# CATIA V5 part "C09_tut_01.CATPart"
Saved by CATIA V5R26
Part number: Part1
Bounding box of the stored display mesh (mm): x -75 to 140, y -40 to 40, z 0 to 100
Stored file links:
  D:\_Deepak\CATIA\CATIA V5 2015 Parts Files\Tutorial Files\Tutorials\c09_catia_v5_6r2015_tut\C09_tut_01.CATPart
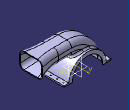
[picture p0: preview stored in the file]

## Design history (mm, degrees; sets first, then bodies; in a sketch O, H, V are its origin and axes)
Body1 (main body)
  Sketch1 on zx-plane, origin (0, 0, 0), H (-1, 0, 0), V (0, 0, 1)
    arc A1 centre (0, 0) radius 60 from (60, 0) to (-60, 0) ccw
    line L1 (-60, 0) -> (60, 0)
    point P1 (-60, 0)
    radius A1 = 60
    coincidence: P1 H
    horizontal: L1 H
  Pad1: profile Sketch1, direction (0, 1, 0), length 40, mirrored extent
  Sketch2 on zx-plane, origin (0, 0, 0), H (-1, 0, 0), V (0, 0, 1)
    point P1 (-82, 100)
    line L1 (-82, 100) -> (-40, 100)
    arc A1 centre (-40, 0) radius 100 from (-40, 100) to (60, 0) cw
    point P4 (60, 0)
    reference projected line E1 (-60, 0) -> (60, 0) from edge [face of Pad1 from Sketch1.L1 | end face of Pad1]
    reference projected point E2 (60, 0) from edge [face of Pad1 from Sketch1.A1 | face of Pad1 from Sketch1.L1]
    reference projected arc E3 centre (0, 0) radius 60 from (60, 0) to (-60, 0) ccw from edge [face of Pad1 from Sketch1.A1 | end face of Pad1]
    distance P1 E1 = 100
    distance P1 V = 82
    horizontal: L1 H
    tangency: A1 L1, A1 E3
    coincidence: P4 E2
  Plane1: type Normal, Curve Sketch2, RefPoint Sketch2.P1, Ratio 0
  Sketch3 on Plane1, origin (82, 0, 0), H (0, 1, 0), V (0, 0, 1)
    line L1 (-29, 100) -> (29, 100)
    line L2 (29, 100) -> (29, 58)
    line L3 (29, 58) -> (-29, 58)
    line L4 (-29, 58) -> (-29, 100)
    reference projected point E1 (0, 100) from Sketch2.P1
    distance L4 V = 29
    length L1 = 58
    length L2 = 42
    horizontal: L1 H, L3 H
    vertical: L2 V, L4 V
    coincidence: L1 E1
  Rib1: profile Sketch3, centre curve Sketch2
  Plane2: type Offset, RefPlane face of Rib1, Offset 58, reversed
  Sketch4 on Plane2, origin (140, 0, 0), H (0, -1, 0), V (0, 0, 1)
    line L1 (36.53, 100) -> (-36.47, 100)
    line L2 (-36.47, 100) -> (-36.47, 47)
    line L3 (-36.47, 47) -> (36.53, 47)
    line L4 (36.53, 47) -> (36.53, 100)
    reference projected line E1 (40, 0) -> (-40, 0) from edge [face of Rib1 | face of Pad1 from Sketch1.A1]
    distance L4 V = 36.53
    distance L1 E1 = 100
    length L2 = 53
    length L1 = 73
    horizontal: L1 H, L3 H
    vertical: L2 V, L4 V
  Loft1: solid, Sections ({boundary Boundary {extract ExtractElem face of Rib1}}; Sketch4), StartFace face of Rib1
  Fillet1: radius 15, on edge [face of Rib1 | face of Rib1] (x3); edge [face of Loft1 | face of Loft1]
  Shell1: ExtOffset 0, Face (face of Rib1; face of Loft1), IntOffset 2.5
  Fillet2: radius 5, on edge [face of Pad1 from Sketch1.A1 | face of Fillet1]
  Sketch5 on end face of Pad1, origin (0, 40, 0), H (-1, 0, 0), V (0, 0, 1)
    arc A1 centre (0, 0) radius 49 from (49, 0) to (-49, 0) ccw
    line L1 (-49, 0) -> (49, 0)
    point P1 (-49, 0)
    radius A1 = 49
    coincidence: P1 H
    horizontal: L1 H
  Pocket1: profile Sketch5, direction (0, -1, 0), through (limit type 6)
  Sketch6 on start face of Pad1, origin (0, -40, 0), H (1, 0, 0), V (0, 0, 1)
    circle A1 centre (0, 0) radius 15
    radius A1 = 15
  Pocket2: profile Sketch6, direction (0, 1, 0), through (limit type 6)
  Sketch7 on end face of Pad1, origin (0, 40, 0), H (-1, 0, 0), V (0, 0, 1)
    line L1 (60, 0) -> (75, 0)
    line L2 (75, 0) -> (75, 4)
    line L3 (75, 4) -> (59.8665, 4)
    point P4 (59.8665, 4)
    reference projected line E1 (-60, 0) -> (60, 0) from edge [face of Rib1 | end face of Pad1]
    reference intersected line E2 (60, 0) -> (-60, 0) from face of Rib1
    reference projected arc E3 centre (0, 0) radius 60 from (60, 0) to (-60, 0) ccw from edge [face of Pad1 from Sketch1.A1 | end face of Pad1]
    projected arc E4 centre (0, 0) radius 60 from (60, 0) to (-60, 0) ccw from edge [face of Pad1 from Sketch1.A1 | end face of Pad1]
    projected arc E5 centre (0, 0) radius 60 from (60, 0) to (59.8665, 4) ccw from edge [face of Pad1 from Sketch1.A1 | end face of Pad1]
    length L2 = 4
    distance L2 V = 75
    horizontal: L1 H, L3 H
    vertical: L2 V
    coincidence: L1 E1, L1 E2, P4 E3
  Pad2: profile Sketch7, direction (0, -1, 0), length 80
  Mirror1: of Pad2, about yz-plane
  Sketch8 on face of Mirror1, origin (0, 0, 4), H (1, 0, 0), V (0, 1, 0)
    point P1 (-67, 30)
    reference projected line E1 (-75, 40) -> (-59.8665, 40) from edge [face of Pad2 from Sketch7.L3 | face of Mirror1]
    reference projected line E2 (-75, 40) -> (-75, -40) from edge [face of Pad2 from Sketch7.L2 | face of Pad2 from Sketch7.L3]
    point P2 (67, 30)
    distance E1 P1 = 10
    distance P1 E2 = 8
    symmetry: P1 P2 V
  Sketch9 on face of Pad2 from Sketch7.L3, origin (-67, 30, 4), H (1, 0, 0), V (0, 1, 0)
    point P1 (0, 0)
    reference projected point E1 (0, 0) from Sketch8.P1
    coincidence: E1 P1
  Hole1: placed by Sketch9, at (-67, 30, 4) direction (0, 0, -1), diameter 4, through (limit type 6)
  RectPattern1: of Hole1, direction 1 instances 4, spacing 20, along edge [face of Pad2 from Sketch7.L2 | face of Pad2 from Sketch7.L3]
  Sketch10 on face of Mirror1, origin (67, 30, 4), H (1, 0, 0), V (0, 1, 0)
    point P1 (0, 0)
    reference projected point E1 (0, 0) from Sketch8.P2
    coincidence: E1 P1
  Hole2: placed by Sketch10, at (67, 30, 4) direction (0, 0, -1), diameter 4, through (limit type 6)
  RectPattern2: of Hole2, direction 1 instances 4, spacing 20, along edge [face of Mirror1 | face of Mirror1]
